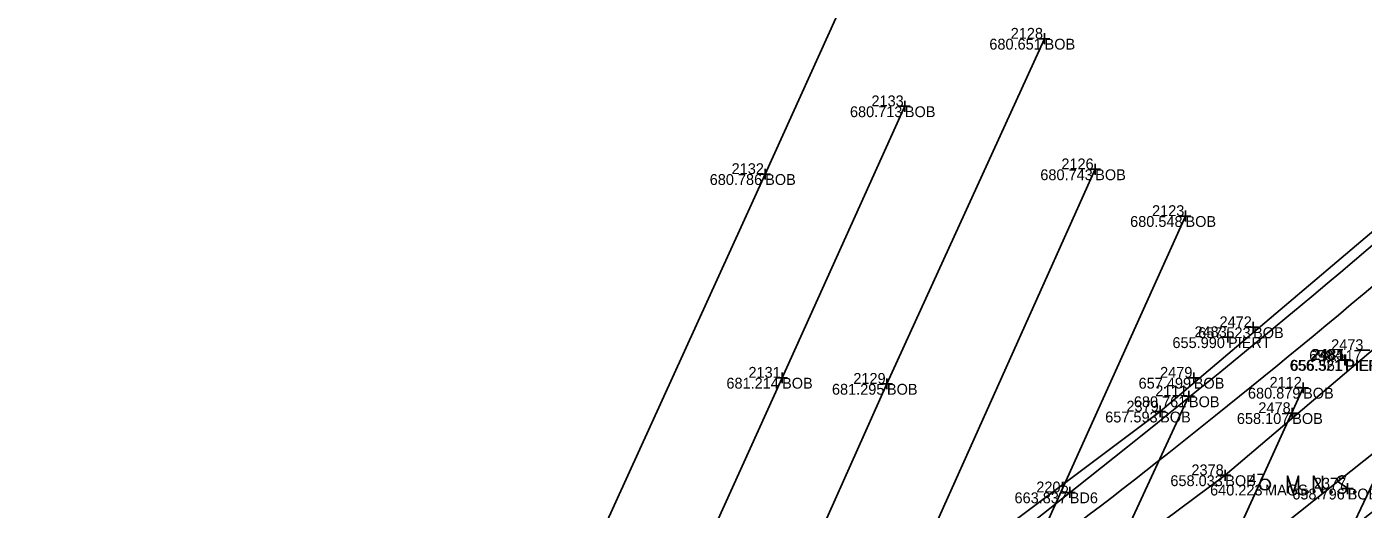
# Model space of a CAD drawing. Extents: x 2197382 to 2204062, y 634117 to 636522.
# Drawn here: x 2202630.7 to 2202753.9, y 635401.4 to 635445.9 of the extents above; entities that cross this region are included whole.
import ezdxf

# ---------------------------------------------------------------- set-up
doc = ezdxf.new("R2010")
doc.units = 0
for name, color, linetype in [('_CIVIL_CONSTRUCTION', 7, 'Continuous'), ('BR_X_SV_Bottom_of_Beam', 7, 'Continuous'), ('BR_X_SV_Bottom_of_Beam_Text', 7, 'Continuous'), ('BR_X_SV_Deck_Top', 7, 'Continuous'), ('BR_X_SV_Deck_Top_Text', 7, 'Continuous'), ('BR_X_SV_Pier_Cap_Top_Text', 7, 'Continuous'), ('GE_P_Alignment_100_Distances', 7, 'Continuous'), ('SH_Border', 7, 'Continuous'), ('SH_Cut_Line', 7, 'Continuous'), ('SH_Data', 7, 'Continuous'), ('SV_P_Control_Cells_Set', 7, 'Continuous')]:
    doc.layers.add(name, color=color, linetype=linetype)

msp = doc.modelspace()

# ---------------------------------------------------------------- linework, layer by layer
at = {"layer": '_CIVIL_CONSTRUCTION'}
for p, q in [((2202724, 635444.82), (2202725, 635444.82)), ((2202724.5, 635445.32), (2202724.5, 635444.32)), ((2202724.5, 635444.82), (2202724.5, 635444.82)), ((2202711.12, 635438.59), (2202712.12, 635438.59)), ((2202711.62, 635439.09), (2202711.62, 635438.09)), ((2202711.62, 635438.59), (2202711.62, 635438.59)), ((2202698.24, 635432.34), (2202699.24, 635432.34)), ((2202698.74, 635432.84), (2202698.74, 635431.84)), ((2202698.74, 635432.34), (2202698.74, 635432.34)), ((2202728.67, 635432.78), (2202729.67, 635432.78)), ((2202729.17, 635433.28), (2202729.17, 635432.28)), ((2202729.17, 635432.78), (2202729.17, 635432.78)), ((2202737.49, 635428.97), (2202737.49, 635427.97)), ((2202736.99, 635428.47), (2202737.99, 635428.47)), ((2202737.49, 635428.47), (2202737.49, 635428.47)), ((2202743.72, 635418.72), (2202743.72, 635417.72)), ((2202741.41, 635417.8), (2202741.41, 635416.8)), ((2202743.22, 635418.22), (2202744.22, 635418.22)), ((2202743.72, 635418.22), (2202743.72, 635418.22)), ((2202740.91, 635417.3), (2202741.91, 635417.3)), ((2202741.41, 635417.3), (2202741.41, 635417.3)), ((2202751.69, 635415.21), (2202752.69, 635415.21)), ((2202751.75, 635415.2), (2202752.75, 635415.2)), ((2202752.19, 635415.71), (2202752.19, 635414.71)), ((2202752.19, 635415.21), (2202752.19, 635415.21)), ((2202752.25, 635415.7), (2202752.25, 635414.7)), ((2202752.25, 635415.2), (2202752.25, 635415.2)), ((2202753.5, 635416.11), (2202754.5, 635416.11)), ((2202700.3, 635414.06), (2202700.3, 635413.06)), ((2202738.25, 635414.06), (2202738.25, 635413.06)), ((2202699.8, 635413.56), (2202700.8, 635413.56)), ((2202700.3, 635413.56), (2202700.3, 635413.56)), ((2202709.47, 635413), (2202710.47, 635413)), ((2202709.97, 635413.5), (2202709.97, 635412.5)), ((2202709.97, 635413), (2202709.97, 635413)), ((2202737.75, 635413.56), (2202738.75, 635413.56)), ((2202738.25, 635413.56), (2202738.25, 635413.56)), ((2202747.83, 635412.64), (2202748.83, 635412.64)), ((2202748.33, 635413.14), (2202748.33, 635412.14)), ((2202748.33, 635412.64), (2202748.33, 635412.64)), ((2202737.31, 635411.85), (2202738.31, 635411.85)), ((2202737.81, 635412.35), (2202737.81, 635411.35)), ((2202737.81, 635411.85), (2202737.81, 635411.85)), ((2202734.65, 635410.44), (2202735.65, 635410.44)), ((2202735.15, 635410.94), (2202735.15, 635409.94)), ((2202735.15, 635410.44), (2202735.15, 635410.44)), ((2202746.83, 635410.3), (2202747.83, 635410.3)), ((2202747.33, 635410.8), (2202747.33, 635409.8)), ((2202747.33, 635410.3), (2202747.33, 635410.3)), ((2202740.66, 635404.57), (2202741.66, 635404.57)), ((2202741.16, 635405.07), (2202741.16, 635404.07)), ((2202741.16, 635404.57), (2202741.16, 635404.57)), ((2202726.32, 635402.99), (2202727.32, 635402.99)), ((2202726.82, 635403.49), (2202726.82, 635402.49)), ((2202726.82, 635402.99), (2202726.82, 635402.99)), ((2202751.94, 635403.34), (2202752.94, 635403.34)), ((2202752.44, 635403.84), (2202752.44, 635402.84)), ((2202752.44, 635403.34), (2202752.44, 635403.34))]:
    msp.add_line(p, q, dxfattribs=at)
at = {"layer": 'BR_X_SV_Bottom_of_Beam'}
for p, q in [((2202698.74, 635432.34), (2202712.5, 635462.79)), ((2202700.3, 635413.56), (2202711.62, 635438.59)), ((2202729.17, 635432.78), (2202714.1, 635399.23)), ((2202721.56, 635393.2), (2202737.49, 635428.47)), ((2202745.38, 635383.92), (2202761.44, 635418.05)), ((2202732.2, 635377.2), (2202748.33, 635412.64)), ((2202737.81, 635411.85), (2202723.29, 635380.55))]:
    msp.add_line(p, q, dxfattribs=at)
for points in [[(2202692.59, 635374.16), (2202701.21, 635393.39), (2202709.97, 635413), (2202724.5, 635444.82)], [(2202692.15, 635358.45), (2202706.56, 635369.16), (2202730.44, 635387.21), (2202776.24, 635423.63), (2202788.52, 635433.73)], [(2202698.74, 635432.34), (2202647, 635318.77), (2202622.9, 635265.64), (2202604.22, 635223.89), (2202566.19, 635137.25)], [(2202513.32, 635270.74), (2202518.46, 635273.22), (2202532.26, 635280.28), (2202548.24, 635288.65), (2202560.65, 635295.12), (2202588.28, 635310.4), (2202608.69, 635322.99), (2202620.52, 635330.21), (2202626.07, 635333.71), (2202636.25, 635340.13), (2202656.93, 635353.89), (2202662.46, 635358.97), (2202720.9, 635399.77), (2202735.15, 635410.44), (2202760.7, 635432.08)], [(2202624.85, 635323.11), (2202626.63, 635325.16), (2202640.9, 635333.25), (2202660.71, 635346.32), (2202681.44, 635361.42), (2202700.99, 635375.17), (2202725.62, 635393.02), (2202741.16, 635404.57), (2202768.03, 635427.42)], [(2202700.3, 635413.56), (2202652.91, 635308.89), (2202632.96, 635265.28), (2202616.35, 635228.13), (2202571.26, 635128.11)]]:
    msp.add_lwpolyline(points, dxfattribs=at)
at = {"layer": 'BR_X_SV_Deck_Top'}
for points in [[(2202430.05, 635233.59), (2202439.74, 635238.51), (2202466.34, 635247.69), (2202507.17, 635268.03), (2202543.72, 635286.4), (2202574.88, 635303.71), (2202604.91, 635320.16), (2202634.13, 635339.4), (2202663.02, 635358.59), (2202692.44, 635376.51), (2202729.25, 635404.45), (2202755.81, 635426.42), (2202769.74, 635438.84)], [(2202458.05, 635216.68), (2202477.12, 635219.98), (2202511.72, 635243.78), (2202554.96, 635262.3), (2202588.01, 635280.67), (2202608.34, 635292.39), (2202640.83, 635312.14), (2202668.15, 635329.95), (2202698.57, 635351.31), (2202722.13, 635368.65), (2202754.6, 635393.43), (2202777.49, 635412.29), (2202789.61, 635422.64)]]:
    msp.add_open_spline(points, degree=3, dxfattribs=at)
at = {"layer": 'GE_P_Alignment_100_Distances'}
for points in [[(2202483.16, 635252.76), (2202495.4, 635258.23), (2202515.21, 635267.82), (2202539.51, 635280.18), (2202556.27, 635289.07), (2202570.79, 635297.09), (2202585.76, 635305.34), (2202607.83, 635319.01), (2202630.78, 635332.65), (2202656.43, 635348.81), (2202675.69, 635362.47), (2202698.98, 635379.18), (2202729.9, 635401.35), (2202753.67, 635420.87), (2202767.82, 635433.18)], [(2202457.67, 635223.28), (2202466.48, 635226.87), (2202500.46, 635242.35), (2202539.48, 635261.18), (2202573.06, 635279.52), (2202585.61, 635286.63), (2202599.84, 635294.84), (2202617.62, 635305.23), (2202642.29, 635320.4), (2202667.37, 635336.77), (2202691.72, 635353.63), (2202713.41, 635369.4), (2202739.64, 635388.97), (2202758.66, 635404.28), (2202770.06, 635413.81)]]:
    msp.add_open_spline(points, degree=3, dxfattribs=at)
at = {"layer": 'SV_P_Control_Cells_Set'}
for points in [[(2202746.91, 635402.91), (2202746.91, 635404.51), (2202747.42, 635402.91), (2202747.9, 635404.51), (2202747.9, 635402.91)], [(2202746.91, 635402.91), (2202746.91, 635404.51), (2202747.42, 635402.91), (2202747.9, 635404.51), (2202747.9, 635402.91)], [(2202749.28, 635402.91), (2202749.28, 635404.51), (2202750.11, 635402.91), (2202750.11, 635404.51)], [(2202749.28, 635402.91), (2202749.28, 635404.51), (2202750.11, 635402.91), (2202750.11, 635404.51)], [(2202752.26, 635404.4), (2202752.24, 635404.42), (2202752.2, 635404.45), (2202752.1, 635404.49), (2202751.98, 635404.51), (2202751.89, 635404.51), (2202751.86, 635404.51), (2202751.72, 635404.47), (2202751.6, 635404.4), (2202751.52, 635404.3), (2202751.5, 635404.2), (2202751.5, 635404.12), (2202751.52, 635404.02), (2202751.61, 635403.93), (2202752.21, 635403.55), (2202752.27, 635403.5), (2202752.29, 635403.45), (2202752.31, 635403.38), (2202752.31, 635403.3), (2202752.3, 635403.23), (2202752.29, 635403.18), (2202752.27, 635403.11), (2202752.25, 635403.06), (2202752.23, 635403.03), (2202752.19, 635402.99), (2202752.16, 635402.96), (2202752.12, 635402.94), (2202752.08, 635402.93), (2202751.98, 635402.91), (2202751.83, 635402.91), (2202751.73, 635402.94), (2202751.59, 635403.03), (2202751.5, 635403.1)], [(2202752.26, 635404.4), (2202752.24, 635404.42), (2202752.2, 635404.45), (2202752.1, 635404.49), (2202751.98, 635404.51), (2202751.89, 635404.51), (2202751.86, 635404.51), (2202751.72, 635404.47), (2202751.6, 635404.4), (2202751.52, 635404.3), (2202751.5, 635404.2), (2202751.5, 635404.12), (2202751.52, 635404.02), (2202751.61, 635403.93), (2202752.21, 635403.55), (2202752.27, 635403.5), (2202752.29, 635403.45), (2202752.31, 635403.38), (2202752.31, 635403.3), (2202752.3, 635403.23), (2202752.29, 635403.18), (2202752.27, 635403.11), (2202752.25, 635403.06), (2202752.23, 635403.03), (2202752.19, 635402.99), (2202752.16, 635402.96), (2202752.12, 635402.94), (2202752.08, 635402.93), (2202751.98, 635402.91), (2202751.83, 635402.91), (2202751.73, 635402.94), (2202751.59, 635403.03), (2202751.5, 635403.1)], [(2202748.68, 635403.13), (2202748.73, 635403.13), (2202748.76, 635403.1), (2202748.8, 635403.05), (2202748.8, 635402.99), (2202748.76, 635402.94), (2202748.73, 635402.91), (2202748.68, 635402.91), (2202748.64, 635402.94), (2202748.61, 635402.99), (2202748.61, 635403.05), (2202748.64, 635403.1), (2202748.68, 635403.13)], [(2202748.68, 635403.13), (2202748.73, 635403.13), (2202748.76, 635403.1), (2202748.8, 635403.05), (2202748.8, 635402.99), (2202748.76, 635402.94), (2202748.73, 635402.91), (2202748.68, 635402.91), (2202748.64, 635402.94), (2202748.61, 635402.99), (2202748.61, 635403.05), (2202748.64, 635403.1), (2202748.68, 635403.13)], [(2202750.89, 635403.13), (2202750.95, 635403.13), (2202750.98, 635403.1), (2202751.01, 635403.05), (2202751.01, 635402.99), (2202750.98, 635402.94), (2202750.95, 635402.91), (2202750.89, 635402.91), (2202750.86, 635402.94), (2202750.83, 635402.99), (2202750.83, 635403.05), (2202750.86, 635403.1), (2202750.89, 635403.13)], [(2202750.89, 635403.13), (2202750.95, 635403.13), (2202750.98, 635403.1), (2202751.01, 635403.05), (2202751.01, 635402.99), (2202750.98, 635402.94), (2202750.95, 635402.91), (2202750.89, 635402.91), (2202750.86, 635402.94), (2202750.83, 635402.99), (2202750.83, 635403.05), (2202750.86, 635403.1), (2202750.89, 635403.13)], [(2202753.07, 635403.13), (2202753.13, 635403.13), (2202753.16, 635403.1), (2202753.2, 635403.05), (2202753.2, 635402.99), (2202753.16, 635402.94), (2202753.13, 635402.91), (2202753.07, 635402.91), (2202753.04, 635402.94), (2202753.01, 635402.99), (2202753.01, 635403.05), (2202753.04, 635403.1), (2202753.07, 635403.13)], [(2202753.07, 635403.13), (2202753.13, 635403.13), (2202753.16, 635403.1), (2202753.2, 635403.05), (2202753.2, 635402.99), (2202753.16, 635402.94), (2202753.13, 635402.91), (2202753.07, 635402.91), (2202753.04, 635402.94), (2202753.01, 635402.99), (2202753.01, 635403.05), (2202753.04, 635403.1), (2202753.07, 635403.13)]]:
    msp.add_lwpolyline(points, dxfattribs=at)
msp.add_circle((2202744.82, 635403.71), 0.497, dxfattribs=at)
msp.add_circle((2202744.82, 635403.71), 0.497, dxfattribs=at)

# ---------------------------------------------------------------- texts
at = {"layer": 'BR_X_SV_Bottom_of_Beam_Text'}
for s, p in [('2128', (2202721.38, 635444.82)), ('680.651', (2202719.41, 635443.82)), ('BOB', (2202724.5, 635443.82)), ('680.713', (2202706.56, 635437.59)), ('2133', (2202708.54, 635438.59)), ('BOB', (2202711.62, 635437.59)), ('2126', (2202726.05, 635432.78)), ('680.786', (2202693.63, 635431.34)), ('2132', (2202695.65, 635432.34)), ('BOB', (2202698.74, 635431.34)), ('680.743', (2202724.11, 635431.78)), ('BOB', (2202729.17, 635431.78)), ('2123', (2202734.41, 635428.47)), ('680.548', (2202732.39, 635427.47)), ('BOB', (2202737.49, 635427.47)), ('2472', (2202740.63, 635418.22)), ('657.523', (2202738.66, 635417.22)), ('BOB', (2202743.72, 635417.22)), ('2473', (2202750.92, 635416.11)), ('658.117', (2202748.9, 635415.11)), ('2131', (2202697.2, 635413.56)), ('2129', (2202706.87, 635413)), ('2479', (2202735.15, 635413.56)), ('681.214', (2202695.17, 635412.56)), ('BOB', (2202700.3, 635412.56)), ('681.295', (2202704.9, 635412)), ('BOB', (2202709.97, 635412)), ('657.499', (2202733.17, 635412.56)), ('2111', (2202734.71, 635411.85)), ('BOB', (2202738.25, 635412.56)), ('680.879', (2202743.25, 635411.64)), ('2112', (2202745.24, 635412.64)), ('BOB', (2202748.33, 635411.64)), ('2379', (2202732.05, 635410.44)), ('680.761', (2202732.73, 635410.85)), ('BOB', (2202737.81, 635410.85)), ('2478', (2202744.21, 635410.3)), ('657.593', (2202730.09, 635409.44)), ('BOB', (2202735.15, 635409.44)), ('658.107', (2202742.23, 635409.3)), ('BOB', (2202747.33, 635409.3)), ('2378', (2202738.04, 635404.57)), ('658.033', (2202736.1, 635403.57)), ('BOB', (2202741.16, 635403.57)), ('2377', (2202749.33, 635403.34)), ('658.796', (2202747.34, 635402.34)), ('BOB', (2202752.44, 635402.34))]:
    msp.add_text(s, height=1, dxfattribs=at).set_placement(p)
at = {"layer": 'BR_X_SV_Deck_Top_Text'}
for s, p in [('2205', (2202723.74, 635402.99)), ('663.837', (2202721.73, 635401.99)), ('BD6', (2202726.82, 635401.99))]:
    msp.add_text(s, height=1, dxfattribs=at).set_placement(p)
at = {"layer": 'BR_X_SV_Pier_Cap_Top_Text'}
for s, p in [('2483', (2202738.32, 635417.3)), ('655.990', (2202736.29, 635416.3)), ('PIERT', (2202741.41, 635416.3)), ('2484', (2202749.04, 635415.21)), ('656.321', (2202747.1, 635414.21)), ('656.561', (2202747.17, 635414.2)), ('2485', (2202749.16, 635415.2)), ('PIERT', (2202752.19, 635414.21)), ('PIERT', (2202752.25, 635414.2))]:
    msp.add_text(s, height=1, dxfattribs=at).set_placement(p)
at = {"layer": 'SH_Border'}
msp.add_text('MAGS', height=1, dxfattribs=at).set_placement((2202744.82, 635402.71))
msp.add_text('MAGS', height=1, dxfattribs=at).set_placement((2202744.82, 635402.71))
at = {"layer": 'SH_Cut_Line'}
msp.add_text('47', height=1, dxfattribs=at).set_placement((2202743.3, 635403.71))
msp.add_text('47', height=1, dxfattribs=at).set_placement((2202743.3, 635403.71))
at = {"layer": 'SH_Data'}
msp.add_text('640.223', height=1, dxfattribs=at).set_placement((2202739.76, 635402.71))
msp.add_text('640.223', height=1, dxfattribs=at).set_placement((2202739.76, 635402.71))

doc.saveas('drawing.dxf')
